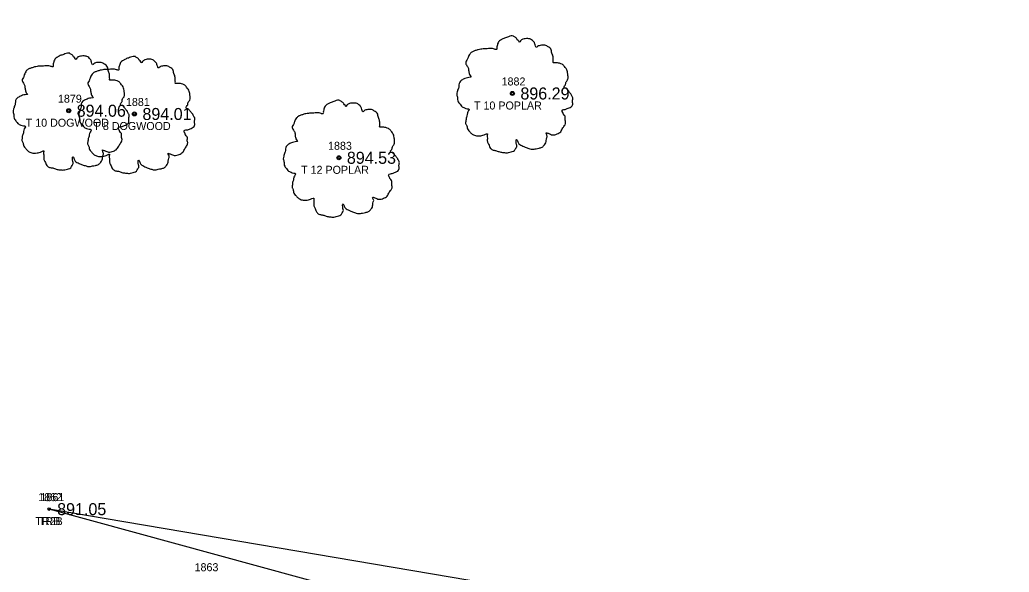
# Model space of a CAD drawing. Extents: x 1448136 to 1453623, y 1125056 to 1128842.
# Drawn here: x 1449747.7 to 1449871.2, y 1126787.2 to 1126856.2 of the extents above; entities that cross this region are included whole.
import ezdxf

# ---------------------------------------------------------------- set-up
doc = ezdxf.new("R2010")
doc.units = 0
for name, color, linetype in [('RD_EX_Fence_Other_txCode', 7, 'Continuous'), ('RD_EX_TX_VEG_ELEV', 7, 'Continuous'), ('RD_EX_VEG', 7, 'Continuous'), ('RD_EX_VEG_txCode', 7, 'Continuous'), ('RD_SMD_Locator', 7, 'Continuous')]:
    doc.layers.add(name, color=color, linetype=linetype)

msp = doc.modelspace()

# ---------------------------------------------------------------- linework, layer by layer
at = {"layer": 'RD_EX_VEG'}
for points in [[(1450497.14, 1126869.56), (1450516.22, 1126848.5), (1450549.56, 1126811.53), (1450532.56, 1126794.68), (1450460.23, 1126747.26), (1450374.14, 1126711.58), (1450359.93, 1126714.38), (1450327.4, 1126704.15), (1450192.75, 1126708.95), (1450138.86, 1126723.3), (1450098.59, 1126713.39), (1450034.93, 1126708.87), (1450011.45, 1126718.54), (1449911.15, 1126743.4), (1449863.97, 1126758.23), (1449819.7, 1126776.41), (1449751.34, 1126795.1)], [(1450056.89, 1126784.04), (1450047.15, 1126748.04), (1450041.18, 1126724.82), (1450011.35, 1126731.86), (1449969.63, 1126743.17), (1449916.46, 1126756.27), (1449872.7, 1126768.68), (1449825.21, 1126782.55), (1449751.34, 1126795.1)]]:
    msp.add_lwpolyline(points, dxfattribs=at)
for centre, radius in [((1449809.19, 1126847), 0.25), ((1449809.18, 1126846.98), 0.0001), ((1449753.78, 1126844.85), 0.25), ((1449753.77, 1126844.83), 0.0001), ((1449761.99, 1126844.44), 0.25), ((1449761.98, 1126844.42), 0.0001), ((1449787.52, 1126838.97), 0.25), ((1449787.51, 1126838.95), 0.0001)]:
    msp.add_circle(centre, radius, dxfattribs=at)
for points in [[(1449809.32, 1126854.17), (1449809.02, 1126854.19), (1449808.7, 1126854.09), (1449808.45, 1126854), (1449808.22, 1126853.92), (1449808, 1126853.82), (1449807.7, 1126853.65), (1449807.47, 1126853.45), (1449807.35, 1126853.2), (1449807.3, 1126852.97), (1449807.25, 1126852.7), (1449807.25, 1126852.52), (1449807.12, 1126852.5), (1449806.97, 1126852.52), (1449806.72, 1126852.6), (1449806.47, 1126852.6), (1449806.22, 1126852.6), (1449805.87, 1126852.57), (1449805.52, 1126852.57), (1449805.25, 1126852.52), (1449804.92, 1126852.47), (1449804.55, 1126852.35), (1449804.2, 1126852.22), (1449803.9, 1126851.97), (1449803.65, 1126851.5), (1449803.52, 1126851.15), (1449803.37, 1126850.9), (1449803.52, 1126850.45), (1449803.7, 1126850.1), (1449803.72, 1126849.9), (1449803.8, 1126849.47), (1449803.9, 1126849.25), (1449804.02, 1126849.05), (1449803.95, 1126849.02), (1449803.57, 1126848.97), (1449803.27, 1126848.87), (1449802.85, 1126848.65), (1449802.62, 1126848.42), (1449802.52, 1126848.1), (1449802.5, 1126847.75), (1449802.4, 1126847.55), (1449802.32, 1126847.27), (1449802.3, 1126847.2), (1449802.25, 1126846.87), (1449802.35, 1126846.42), (1449802.37, 1126846.07), (1449802.5, 1126845.85), (1449802.65, 1126845.67), (1449802.82, 1126845.42), (1449803.22, 1126845.2), (1449803.55, 1126845.1), (1449803.75, 1126845.07), (1449803.57, 1126844.57), (1449803.52, 1126844.22), (1449803.4, 1126843.82), (1449803.4, 1126843.75), (1449803.35, 1126843.27), (1449803.5, 1126842.95), (1449803.57, 1126842.58), (1449803.75, 1126842.35), (1449804.02, 1126842.05), (1449804.35, 1126841.83), (1449804.85, 1126841.7), (1449805.25, 1126841.73), (1449805.82, 1126841.9), (1449806.07, 1126841.98), (1449806.05, 1126841.8), (1449806.07, 1126841.43), (1449806.07, 1126841), (1449806.22, 1126840.68), (1449806.32, 1126840.4), (1449806.47, 1126840.15), (1449806.8, 1126839.93), (1449807.2, 1126839.85), (1449807.62, 1126839.7), (1449808.07, 1126839.63), (1449808.57, 1126839.6), (1449809.17, 1126839.75), (1449809.45, 1126839.88), (1449809.55, 1126840.05), (1449809.75, 1126840.43), (1449809.7, 1126840.65), (1449809.72, 1126841.25), (1449809.82, 1126841.08), (1449810, 1126840.73), (1449810.5, 1126840.43), (1449810.9, 1126840.25), (1449811.37, 1126840.1), (1449811.67, 1126840.03), (1449812.14, 1126840.1), (1449812.52, 1126840.18), (1449812.89, 1126840.3), (1449813.19, 1126840.58), (1449813.37, 1126840.85), (1449813.42, 1126841.13), (1449813.49, 1126841.5), (1449813.54, 1126841.68)], [(1449813.54, 1126841.68), (1449813.47, 1126841.85), (1449813.42, 1126842.1), (1449813.49, 1126842.08), (1449813.67, 1126842.03), (1449813.94, 1126841.9), (1449814.17, 1126841.83), (1449814.49, 1126841.85), (1449814.77, 1126841.95), (1449815.22, 1126842.23), (1449815.49, 1126842.7), (1449815.77, 1126843.1), (1449815.84, 1126843.42), (1449815.79, 1126843.65), (1449815.77, 1126844.15), (1449815.57, 1126844.4), (1449815.52, 1126844.52), (1449815.42, 1126844.92), (1449815.49, 1126844.97), (1449815.77, 1126845.02), (1449816.14, 1126845.15), (1449816.42, 1126845.27), (1449816.64, 1126845.45), (1449816.72, 1126845.67), (1449816.69, 1126846.07), (1449816.74, 1126846.47), (1449816.67, 1126846.62), (1449816.57, 1126846.77), (1449816.49, 1126846.97), (1449816.34, 1126847.12), (1449816.24, 1126847.27), (1449816.14, 1126847.37), (1449816.02, 1126847.52), (1449815.84, 1126847.65), (1449815.69, 1126847.7), (1449815.64, 1126847.85), (1449815.79, 1126848.05), (1449815.84, 1126848.15), (1449815.87, 1126848.37), (1449816.09, 1126848.72), (1449816.14, 1126849.12), (1449816.09, 1126849.55), (1449816.04, 1126849.82), (1449815.89, 1126850.1), (1449815.69, 1126850.35), (1449815.57, 1126850.52), (1449815.39, 1126850.65), (1449815.07, 1126850.77), (1449814.82, 1126850.82), (1449814.47, 1126850.82), (1449814.27, 1126850.87), (1449814.29, 1126850.92), (1449814.29, 1126851.07), (1449814.29, 1126851.35), (1449814.22, 1126851.8), (1449814.07, 1126852.3), (1449814.07, 1126852.32), (1449813.97, 1126852.57), (1449813.74, 1126852.77), (1449813.57, 1126852.87), (1449813.37, 1126853), (1449813.12, 1126853.02), (1449812.82, 1126853.02), (1449812.54, 1126852.97), (1449812.34, 1126852.87), (1449812.17, 1126852.75), (1449812.09, 1126852.9), (1449811.99, 1126853.2), (1449811.94, 1126853.35), (1449811.8, 1126853.52), (1449811.57, 1126853.72), (1449811.12, 1126853.85), (1449810.5, 1126853.77), (1449810.2, 1126853.57), (1449810.05, 1126853.4), (1449810, 1126853.52), (1449809.8, 1126853.72), (1449809.7, 1126853.9), (1449809.52, 1126854.02), (1449809.37, 1126854.12), (1449809.27, 1126854.17)], [(1449753.92, 1126852.02), (1449753.62, 1126852.04), (1449753.29, 1126851.94), (1449753.04, 1126851.84), (1449752.82, 1126851.77), (1449752.59, 1126851.67), (1449752.29, 1126851.49), (1449752.07, 1126851.29), (1449751.94, 1126851.04), (1449751.89, 1126850.82), (1449751.84, 1126850.54), (1449751.84, 1126850.37), (1449751.72, 1126850.34), (1449751.57, 1126850.37), (1449751.32, 1126850.44), (1449751.07, 1126850.44), (1449750.82, 1126850.44), (1449750.47, 1126850.42), (1449750.12, 1126850.42), (1449749.84, 1126850.37), (1449749.52, 1126850.32), (1449749.14, 1126850.19), (1449748.79, 1126850.07), (1449748.49, 1126849.82), (1449748.24, 1126849.34), (1449748.12, 1126848.99), (1449747.97, 1126848.74), (1449748.12, 1126848.29), (1449748.29, 1126847.94), (1449748.32, 1126847.74), (1449748.39, 1126847.32), (1449748.49, 1126847.09), (1449748.62, 1126846.89), (1449748.54, 1126846.87), (1449748.17, 1126846.82), (1449747.87, 1126846.72), (1449747.44, 1126846.49), (1449747.22, 1126846.27), (1449747.12, 1126845.94), (1449747.09, 1126845.59), (1449746.99, 1126845.39), (1449746.92, 1126845.12), (1449746.89, 1126845.04), (1449746.84, 1126844.72), (1449746.94, 1126844.27), (1449746.97, 1126843.92), (1449747.09, 1126843.69), (1449747.24, 1126843.52), (1449747.42, 1126843.27), (1449747.82, 1126843.05), (1449748.14, 1126842.95), (1449748.34, 1126842.92), (1449748.17, 1126842.42), (1449748.12, 1126842.07), (1449747.99, 1126841.67), (1449747.99, 1126841.6), (1449747.94, 1126841.12), (1449748.09, 1126840.8), (1449748.17, 1126840.42), (1449748.34, 1126840.2), (1449748.62, 1126839.9), (1449748.94, 1126839.67), (1449749.44, 1126839.55), (1449749.84, 1126839.57), (1449750.42, 1126839.75), (1449750.67, 1126839.82), (1449750.64, 1126839.65), (1449750.67, 1126839.27), (1449750.67, 1126838.85), (1449750.82, 1126838.52), (1449750.92, 1126838.25), (1449751.07, 1126838), (1449751.39, 1126837.77), (1449751.79, 1126837.7), (1449752.22, 1126837.55), (1449752.67, 1126837.47), (1449753.17, 1126837.45), (1449753.77, 1126837.6), (1449754.04, 1126837.72), (1449754.14, 1126837.9), (1449754.34, 1126838.27), (1449754.29, 1126838.5), (1449754.32, 1126839.1), (1449754.42, 1126838.92), (1449754.59, 1126838.57), (1449755.09, 1126838.27), (1449755.49, 1126838.1), (1449755.96, 1126837.95), (1449756.26, 1126837.87), (1449756.74, 1126837.95), (1449757.11, 1126838.02), (1449757.49, 1126838.15), (1449757.79, 1126838.42), (1449757.96, 1126838.7), (1449758.01, 1126838.97), (1449758.09, 1126839.35), (1449758.14, 1126839.52)], [(1449758.14, 1126839.52), (1449758.06, 1126839.7), (1449758.01, 1126839.95), (1449758.09, 1126839.92), (1449758.26, 1126839.87), (1449758.54, 1126839.75), (1449758.76, 1126839.67), (1449759.09, 1126839.7), (1449759.36, 1126839.8), (1449759.81, 1126840.07), (1449760.09, 1126840.55), (1449760.36, 1126840.95), (1449760.44, 1126841.27), (1449760.39, 1126841.5), (1449760.36, 1126842), (1449760.16, 1126842.25), (1449760.11, 1126842.37), (1449760.01, 1126842.77), (1449760.09, 1126842.82), (1449760.36, 1126842.87), (1449760.74, 1126843), (1449761.01, 1126843.12), (1449761.24, 1126843.3), (1449761.31, 1126843.52), (1449761.29, 1126843.92), (1449761.34, 1126844.32), (1449761.26, 1126844.47), (1449761.16, 1126844.62), (1449761.09, 1126844.82), (1449760.94, 1126844.97), (1449760.84, 1126845.12), (1449760.74, 1126845.22), (1449760.61, 1126845.37), (1449760.44, 1126845.49), (1449760.29, 1126845.54), (1449760.24, 1126845.69), (1449760.39, 1126845.89), (1449760.44, 1126845.99), (1449760.46, 1126846.22), (1449760.69, 1126846.57), (1449760.74, 1126846.97), (1449760.69, 1126847.39), (1449760.64, 1126847.67), (1449760.49, 1126847.94), (1449760.29, 1126848.19), (1449760.16, 1126848.37), (1449759.99, 1126848.49), (1449759.66, 1126848.62), (1449759.41, 1126848.67), (1449759.06, 1126848.67), (1449758.86, 1126848.72), (1449758.89, 1126848.77), (1449758.89, 1126848.92), (1449758.89, 1126849.19), (1449758.81, 1126849.64), (1449758.66, 1126850.14), (1449758.66, 1126850.17), (1449758.56, 1126850.42), (1449758.34, 1126850.62), (1449758.16, 1126850.72), (1449757.96, 1126850.84), (1449757.71, 1126850.87), (1449757.41, 1126850.87), (1449757.14, 1126850.82), (1449756.94, 1126850.72), (1449756.76, 1126850.59), (1449756.69, 1126850.74), (1449756.59, 1126851.04), (1449756.54, 1126851.19), (1449756.39, 1126851.37), (1449756.16, 1126851.57), (1449755.71, 1126851.69), (1449755.09, 1126851.62), (1449754.79, 1126851.42), (1449754.64, 1126851.24), (1449754.59, 1126851.37), (1449754.39, 1126851.57), (1449754.29, 1126851.74), (1449754.12, 1126851.87), (1449753.97, 1126851.97), (1449753.87, 1126852.02)], [(1449762.12, 1126851.6), (1449761.82, 1126851.63), (1449761.5, 1126851.53), (1449761.25, 1126851.43), (1449761.02, 1126851.35), (1449760.8, 1126851.25), (1449760.5, 1126851.08), (1449760.27, 1126850.88), (1449760.15, 1126850.63), (1449760.1, 1126850.4), (1449760.05, 1126850.13), (1449760.05, 1126849.95), (1449759.92, 1126849.93), (1449759.77, 1126849.95), (1449759.52, 1126850.03), (1449759.27, 1126850.03), (1449759.02, 1126850.03), (1449758.67, 1126850), (1449758.32, 1126850), (1449758.05, 1126849.95), (1449757.72, 1126849.9), (1449757.35, 1126849.78), (1449757, 1126849.65), (1449756.7, 1126849.4), (1449756.45, 1126848.93), (1449756.32, 1126848.58), (1449756.17, 1126848.33), (1449756.32, 1126847.88), (1449756.5, 1126847.53), (1449756.52, 1126847.33), (1449756.6, 1126846.9), (1449756.7, 1126846.68), (1449756.82, 1126846.48), (1449756.75, 1126846.46), (1449756.37, 1126846.41), (1449756.07, 1126846.31), (1449755.65, 1126846.08), (1449755.42, 1126845.86), (1449755.32, 1126845.53), (1449755.3, 1126845.18), (1449755.2, 1126844.98), (1449755.12, 1126844.71), (1449755.1, 1126844.63), (1449755.05, 1126844.31), (1449755.15, 1126843.86), (1449755.17, 1126843.51), (1449755.3, 1126843.28), (1449755.45, 1126843.11), (1449755.62, 1126842.86), (1449756.02, 1126842.63), (1449756.35, 1126842.53), (1449756.55, 1126842.51), (1449756.37, 1126842.01), (1449756.32, 1126841.66), (1449756.2, 1126841.26), (1449756.2, 1126841.18), (1449756.15, 1126840.71), (1449756.3, 1126840.38), (1449756.37, 1126840.01), (1449756.55, 1126839.78), (1449756.82, 1126839.48), (1449757.15, 1126839.26), (1449757.65, 1126839.13), (1449758.05, 1126839.16), (1449758.62, 1126839.33), (1449758.87, 1126839.41), (1449758.85, 1126839.23), (1449758.87, 1126838.86), (1449758.87, 1126838.43), (1449759.02, 1126838.11), (1449759.12, 1126837.83), (1449759.27, 1126837.58), (1449759.6, 1126837.36), (1449760, 1126837.28), (1449760.42, 1126837.13), (1449760.87, 1126837.06), (1449761.37, 1126837.03), (1449761.97, 1126837.18), (1449762.25, 1126837.31), (1449762.35, 1126837.48), (1449762.55, 1126837.86), (1449762.5, 1126838.08), (1449762.52, 1126838.68), (1449762.62, 1126838.51), (1449762.8, 1126838.16), (1449763.3, 1126837.86), (1449763.7, 1126837.68), (1449764.17, 1126837.53), (1449764.47, 1126837.46), (1449764.95, 1126837.53), (1449765.32, 1126837.61), (1449765.7, 1126837.73), (1449765.99, 1126838.01), (1449766.17, 1126838.28), (1449766.22, 1126838.56), (1449766.29, 1126838.93), (1449766.34, 1126839.11)], [(1449766.34, 1126839.11), (1449766.27, 1126839.28), (1449766.22, 1126839.53), (1449766.29, 1126839.51), (1449766.47, 1126839.46), (1449766.74, 1126839.33), (1449766.97, 1126839.26), (1449767.29, 1126839.28), (1449767.57, 1126839.38), (1449768.02, 1126839.66), (1449768.29, 1126840.13), (1449768.57, 1126840.53), (1449768.64, 1126840.86), (1449768.59, 1126841.08), (1449768.57, 1126841.58), (1449768.37, 1126841.83), (1449768.32, 1126841.96), (1449768.22, 1126842.36), (1449768.29, 1126842.41), (1449768.57, 1126842.46), (1449768.94, 1126842.58), (1449769.22, 1126842.71), (1449769.44, 1126842.88), (1449769.52, 1126843.11), (1449769.49, 1126843.51), (1449769.54, 1126843.91), (1449769.47, 1126844.06), (1449769.37, 1126844.21), (1449769.29, 1126844.41), (1449769.14, 1126844.56), (1449769.04, 1126844.71), (1449768.94, 1126844.81), (1449768.82, 1126844.96), (1449768.64, 1126845.08), (1449768.49, 1126845.13), (1449768.44, 1126845.28), (1449768.59, 1126845.48), (1449768.64, 1126845.58), (1449768.67, 1126845.81), (1449768.89, 1126846.16), (1449768.94, 1126846.55), (1449768.89, 1126846.98), (1449768.84, 1126847.25), (1449768.69, 1126847.53), (1449768.49, 1126847.78), (1449768.37, 1126847.95), (1449768.19, 1126848.08), (1449767.87, 1126848.2), (1449767.62, 1126848.25), (1449767.27, 1126848.25), (1449767.07, 1126848.3), (1449767.09, 1126848.35), (1449767.09, 1126848.5), (1449767.09, 1126848.78), (1449767.02, 1126849.23), (1449766.87, 1126849.73), (1449766.87, 1126849.75), (1449766.77, 1126850), (1449766.54, 1126850.2), (1449766.37, 1126850.3), (1449766.17, 1126850.43), (1449765.92, 1126850.45), (1449765.62, 1126850.45), (1449765.35, 1126850.4), (1449765.15, 1126850.3), (1449764.97, 1126850.18), (1449764.9, 1126850.33), (1449764.8, 1126850.63), (1449764.75, 1126850.78), (1449764.6, 1126850.95), (1449764.37, 1126851.15), (1449763.92, 1126851.28), (1449763.3, 1126851.2), (1449763, 1126851), (1449762.85, 1126850.83), (1449762.8, 1126850.95), (1449762.6, 1126851.15), (1449762.5, 1126851.33), (1449762.32, 1126851.45), (1449762.17, 1126851.55), (1449762.07, 1126851.6)], [(1449787.65, 1126846.14), (1449787.35, 1126846.16), (1449787.03, 1126846.06), (1449786.78, 1126845.96), (1449786.55, 1126845.89), (1449786.33, 1126845.79), (1449786.03, 1126845.61), (1449785.8, 1126845.41), (1449785.68, 1126845.16), (1449785.63, 1126844.94), (1449785.58, 1126844.67), (1449785.58, 1126844.49), (1449785.45, 1126844.47), (1449785.3, 1126844.49), (1449785.05, 1126844.57), (1449784.8, 1126844.57), (1449784.55, 1126844.57), (1449784.2, 1126844.54), (1449783.85, 1126844.54), (1449783.58, 1126844.49), (1449783.25, 1126844.44), (1449782.88, 1126844.32), (1449782.53, 1126844.19), (1449782.23, 1126843.94), (1449781.98, 1126843.47), (1449781.85, 1126843.12), (1449781.7, 1126842.87), (1449781.85, 1126842.42), (1449782.03, 1126842.07), (1449782.05, 1126841.87), (1449782.13, 1126841.44), (1449782.23, 1126841.22), (1449782.35, 1126841.02), (1449782.28, 1126840.99), (1449781.9, 1126840.94), (1449781.6, 1126840.84), (1449781.18, 1126840.62), (1449780.95, 1126840.39), (1449780.85, 1126840.07), (1449780.83, 1126839.72), (1449780.73, 1126839.52), (1449780.65, 1126839.24), (1449780.63, 1126839.17), (1449780.58, 1126838.84), (1449780.68, 1126838.39), (1449780.7, 1126838.04), (1449780.83, 1126837.82), (1449780.98, 1126837.64), (1449781.15, 1126837.39), (1449781.55, 1126837.17), (1449781.88, 1126837.07), (1449782.08, 1126837.04), (1449781.9, 1126836.54), (1449781.85, 1126836.19), (1449781.73, 1126835.79), (1449781.73, 1126835.72), (1449781.68, 1126835.24), (1449781.83, 1126834.92), (1449781.9, 1126834.54), (1449782.08, 1126834.32), (1449782.35, 1126834.02), (1449782.68, 1126833.79), (1449783.18, 1126833.67), (1449783.58, 1126833.69), (1449784.15, 1126833.87), (1449784.4, 1126833.94), (1449784.38, 1126833.77), (1449784.4, 1126833.39), (1449784.4, 1126832.97), (1449784.55, 1126832.65), (1449784.65, 1126832.37), (1449784.8, 1126832.12), (1449785.13, 1126831.9), (1449785.53, 1126831.82), (1449785.95, 1126831.67), (1449786.4, 1126831.6), (1449786.9, 1126831.57), (1449787.5, 1126831.72), (1449787.78, 1126831.85), (1449787.88, 1126832.02), (1449788.08, 1126832.4), (1449788.03, 1126832.62), (1449788.05, 1126833.22), (1449788.15, 1126833.05), (1449788.33, 1126832.7), (1449788.83, 1126832.4), (1449789.23, 1126832.22), (1449789.7, 1126832.07), (1449790, 1126832), (1449790.48, 1126832.07), (1449790.85, 1126832.15), (1449791.22, 1126832.27), (1449791.52, 1126832.55), (1449791.7, 1126832.82), (1449791.75, 1126833.1), (1449791.82, 1126833.47), (1449791.87, 1126833.64)], [(1449791.87, 1126833.64), (1449791.8, 1126833.82), (1449791.75, 1126834.07), (1449791.82, 1126834.04), (1449792, 1126833.99), (1449792.27, 1126833.87), (1449792.5, 1126833.79), (1449792.82, 1126833.82), (1449793.1, 1126833.92), (1449793.55, 1126834.19), (1449793.82, 1126834.67), (1449794.1, 1126835.07), (1449794.17, 1126835.39), (1449794.12, 1126835.62), (1449794.1, 1126836.12), (1449793.9, 1126836.37), (1449793.85, 1126836.49), (1449793.75, 1126836.89), (1449793.82, 1126836.94), (1449794.1, 1126836.99), (1449794.47, 1126837.12), (1449794.75, 1126837.24), (1449794.97, 1126837.42), (1449795.05, 1126837.64), (1449795.02, 1126838.04), (1449795.07, 1126838.44), (1449795, 1126838.59), (1449794.9, 1126838.74), (1449794.82, 1126838.94), (1449794.67, 1126839.09), (1449794.57, 1126839.24), (1449794.47, 1126839.34), (1449794.35, 1126839.49), (1449794.17, 1126839.62), (1449794.02, 1126839.67), (1449793.97, 1126839.82), (1449794.12, 1126840.02), (1449794.17, 1126840.12), (1449794.2, 1126840.34), (1449794.42, 1126840.69), (1449794.47, 1126841.09), (1449794.42, 1126841.52), (1449794.37, 1126841.79), (1449794.22, 1126842.07), (1449794.02, 1126842.32), (1449793.9, 1126842.49), (1449793.72, 1126842.62), (1449793.4, 1126842.74), (1449793.15, 1126842.79), (1449792.8, 1126842.79), (1449792.6, 1126842.84), (1449792.62, 1126842.89), (1449792.62, 1126843.04), (1449792.62, 1126843.32), (1449792.55, 1126843.77), (1449792.4, 1126844.27), (1449792.4, 1126844.29), (1449792.3, 1126844.54), (1449792.07, 1126844.74), (1449791.9, 1126844.84), (1449791.7, 1126844.96), (1449791.45, 1126844.99), (1449791.15, 1126844.99), (1449790.88, 1126844.94), (1449790.68, 1126844.84), (1449790.5, 1126844.71), (1449790.43, 1126844.86), (1449790.33, 1126845.16), (1449790.28, 1126845.31), (1449790.13, 1126845.49), (1449789.9, 1126845.69), (1449789.45, 1126845.81), (1449788.83, 1126845.74), (1449788.53, 1126845.54), (1449788.38, 1126845.36), (1449788.33, 1126845.49), (1449788.13, 1126845.69), (1449788.03, 1126845.86), (1449787.85, 1126845.99), (1449787.7, 1126846.09), (1449787.6, 1126846.14)]]:
    msp.add_spline(points, degree=3, dxfattribs=at)
at = {"layer": 'RD_SMD_Locator'}
for centre in [(1449809.19, 1126847), (1449753.78, 1126844.85), (1449761.99, 1126844.44), (1449787.52, 1126838.97), (1449751.34, 1126795.1), (1449751.34, 1126795.1)]:
    msp.add_circle(centre, 0.15, dxfattribs=at)

# ---------------------------------------------------------------- texts
at = {"layer": 'RD_EX_Fence_Other_txCode'}
msp.add_text('1863', height=1, dxfattribs=at).set_placement((1449769.5, 1126787.35))
at = {"layer": 'RD_EX_TX_VEG_ELEV'}
for s, p in [('896.29', (1449810.19, 1126846.25)), ('894.06', (1449754.78, 1126844.1)), ('894.01', (1449762.99, 1126843.69)), ('894.53', (1449788.52, 1126838.22)), ('891.05', (1449752.34, 1126794.35)), ('891.05', (1449752.34, 1126794.35))]:
    msp.add_text(s, height=1.5, dxfattribs=at).set_placement(p)
at = {"layer": 'RD_EX_VEG_txCode'}
for s, p in [('1882', (1449807.84, 1126848)), ('1879', (1449752.44, 1126845.85)), ('1881', (1449760.93, 1126845.44)), ('T 10 POPLAR', (1449804.39, 1126845)), ('T 10 DOGWOOD', (1449748.41, 1126842.85)), ('T 8 DOGWOOD', (1449756.86, 1126842.44)), ('1883', (1449786.17, 1126839.97)), ('T 12 POPLAR', (1449782.8, 1126836.97)), ('1862', (1449749.97, 1126796.1)), ('1861', (1449750.25, 1126796.1)), ('TR2B', (1449749.62, 1126793.1)), ('TRB', (1449750.07, 1126793.1))]:
    msp.add_text(s, height=1, dxfattribs=at).set_placement(p)

doc.saveas('drawing.dxf')
